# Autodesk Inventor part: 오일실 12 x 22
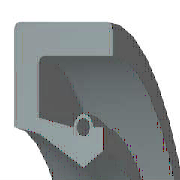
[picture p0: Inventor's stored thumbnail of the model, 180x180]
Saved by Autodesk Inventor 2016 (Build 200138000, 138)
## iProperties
IsCustomPart: 0
Created: 2015-10
Part Number: 오일실 12 x 22
Material: 고무
Description: 오일-실
Document SubType Name: Modeling
Standard: KS B 2804
Designer: mdu
Standards Organization: KS
Language: ko-KR
Size Designation: S - 12 22 7
Categories: <MemberInstance><Categories><Category DisplayName="샤프트 부품" InternalName="7f7aeb1f-a693-4053-b835-cee3144e0d98" Mnemonic="SHFT"><Category DisplayName="실링" Intern
Density: 0.93 g/cm^3
Appearance: 고무 - 검은색 - 버전 1.1
Author: mdu
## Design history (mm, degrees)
revolve "본체" stored, may be unused: angle "d17" = 90 deg
revolve "스프링1" stored, may be unused: angle "d18" = 90 deg
body "Solid1"
sketch "스케치1"
  geometry: L1 (0, 11)-(7, 11); L2 (7, 11)-(7, 9.75); L3 (7, 9.75)-(1.75, 9.75); L4 (0, 11)-(0, 8.1); L5 (0, 8.1)-(1.75, 7.75); L6 (1.75, 7.75)-(4.9, 6); L7 (4.9, 6)-(0, 6); L8 (6.3, 6.875)-(6.3, 8.1); L9 (0, 0)-(9.586, 0) reference; L10 (4.9, 6)-(6.3, 6.875); L11 (0, 18)-(0, -3) reference; L12 (-1.917, 0)-(11.503, 0) reference; L13 (4.2, 8.1)-(1.75, 8.59); L14 (1.75, 8.59)-(1.75, 9.75); L15 (6.3, 8.1)-(5.6, 8.1); C1 r 0.455 at (4.9, 8.1); A1 r 0.7 centre (4.9, 8.1) between (5.6, 8.1) and (4.2, 8.1)
  constraints: 26 end point, 5 horizontal alignment, 4 perpendicular, 2 centre point, 2 collinear, 2 horizontal, 2 parallel, 2 point on circle, 2 point on line, 2 vertical alignment, 1 coincident
  dimensions: "d0" = 22 diameter of L1 L9 (= SD2); "d1" = 13.75 diameter of L8.start L9 (= ABDM); "d2" = 1.25 distance of L1.end L2.end (computed from SD); "d3" = 0.91 diameter of C1 (= SPDI); "d4" = 1.4 diameter of A1 (= SPDA); "d5" = 12 diameter of L6.end L9 (= NND); "d6" = 15.5 diameter of L5.end L9 (= TKDM); "d7" = 16.2 diameter of L4.end L9 (= HLDM); "d8" = 4.9 distance from line of C1.centre L4 (= SPDST); "d9" = 6.3 distance between parallel lines of L8 L4 (= SDI); "d10" = 7 distance between parallel lines of L2 L4 (= SWDT); "d12" = 1.75 distance between parallel lines of L14 L4 (= SD)
fillet "모깎기1" dims "d11" = 0.3 (= RR)
other parameters: "SD2" = 22 [user parameter; used in 1 equation term], "SWDT" = 7 [user parameter; used in 1 equation term], "RR" = 0.3 [user parameter; used in 1 equation term], "SD" = 1.75 [user parameter; used in 2 equation terms], "NND" = 12 [user parameter; used in 1 equation term], "SPDA" = 1.4 [user parameter; used in 1 equation term], "SPDI" = 0.91 [user parameter; used in 1 equation term], "TKDM" = 15.5 [user parameter; used in 1 equation term], "HLDM" = 16.2 [user parameter; used in 1 equation term], "ABDM" = 13.75 [user parameter; used in 1 equation term], "SDI" = 6.3 [user parameter; used in 1 equation term], "SPDST" = 4.9 [user parameter; used in 1 equation term], "d13" = 0, "d14" = 0, "d15" = 0, "LAB" = 0.35 [user parameter]
